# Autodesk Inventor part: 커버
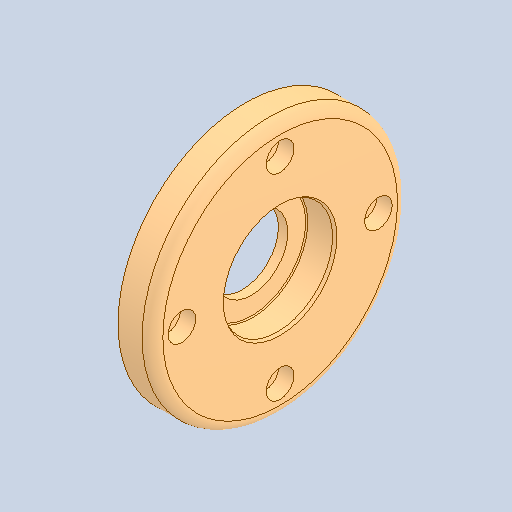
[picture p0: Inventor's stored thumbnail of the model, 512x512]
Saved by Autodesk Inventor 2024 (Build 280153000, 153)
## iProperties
Created: 2024-11
Part Number: 커버
Material: 알루미늄 6061
Document SubType Name: Modeling
Designer: user
Density: 2.7 g/cm^3
Appearance: 기본값
Author: jhkim
Sending System: Autodesk Inventor 2025
Preprocessor: ST-DEVELOPER v20
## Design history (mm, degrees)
node "커버1"
node "솔리드2"
node "솔리드1"
